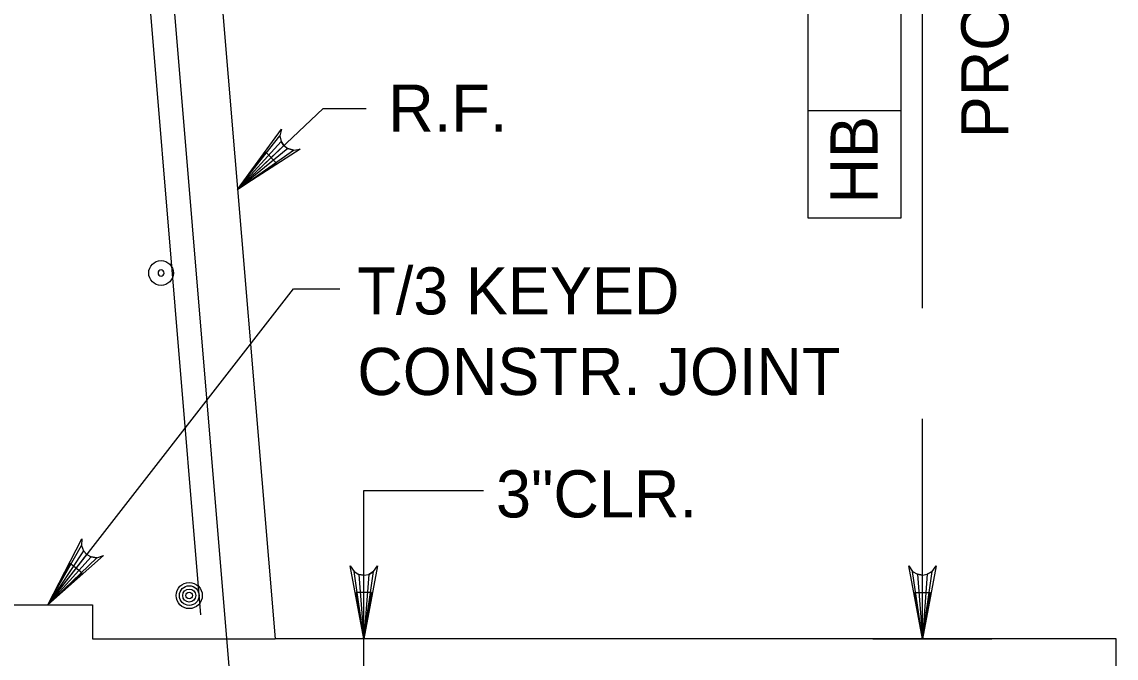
# Model space of a CAD drawing. Extents: x 638255 to 640306, y 296059 to 298435.
# Drawn here: x 639132.2 to 639201.8, y 297021.7 to 297062.2 of the extents above; entities that cross this region are included whole.
import ezdxf

# ---------------------------------------------------------------- set-up
doc = ezdxf.new("R2010")
doc.units = 0
for name, color, linetype in [('3', 7, 'Continuous'), ('Level 3', 7, 'Continuous'), ('Level 4', 7, 'Continuous'), ('Level 5', 7, 'Continuous'), ('Level 6', 7, 'Continuous'), ('Level 7', 7, 'Continuous'), ('Level 9', 7, 'Continuous')]:
    doc.layers.add(name, color=color, linetype=linetype)

# ---------------------------------------------------------------- blocks, each defined once
blk = doc.blocks.new('B')
at = {"layer": '3'}
blk.add_circle((0, 0), 0.16, dxfattribs=at)
for start, end in [(0, 180), (180, 0)]:
    blk.add_arc((0, 0), 0.0391, start, end, dxfattribs=at)

msp = doc.modelspace()

# ---------------------------------------------------------------- linework, layer by layer
at = {"layer": 'Level 3'}
for p, q in [((639189.499, 297043.979), (639189.499, 297093.526)), ((639182.231, 297056.542), (639182.231, 297084.942)), ((639188.123, 297084.942), (639188.123, 297049.709)), ((639145.904, 297051.541), (639151.36, 297056.692)), ((639151.36, 297056.692), (639154.088, 297056.692)), ((639182.231, 297049.709), (639182.231, 297056.542)), ((639188.123, 297056.542), (639182.231, 297056.542)), ((639188.123, 297049.709), (639182.231, 297049.709)), ((639133.823, 297025.106), (639149.464, 297045.222)), ((639149.464, 297045.222), (639152.41, 297045.222)), ((639189.499, 297022.949), (639189.499, 297036.945)), ((639153.939, 297032.379), (639161.559, 297032.379)), ((639186.331, 297022.948), (639193.919, 297022.948))]:
    msp.add_line(p, q, dxfattribs=at)
for points in [[(639145.904, 297051.541), (639148.688, 297055.369), (639148.597, 297054.941), (639148.678, 297054.588), (639148.853, 297054.326), (639149.106, 297054.134), (639149.454, 297054.034), (639149.886, 297054.101), (639145.904, 297051.541), (639149.454, 297054.034), (639149.106, 297054.134), (639145.904, 297051.541), (639148.853, 297054.326), (639148.678, 297054.588), (639145.904, 297051.541), (639148.597, 297054.941)], [(639133.823, 297025.106), (639135.99, 297029.313), (639135.965, 297028.878), (639136.098, 297028.541), (639136.312, 297028.306), (639136.591, 297028.159), (639136.95, 297028.113), (639137.366, 297028.244), (639133.823, 297025.106), (639136.95, 297028.113), (639136.591, 297028.159), (639133.823, 297025.106), (639136.312, 297028.306), (639136.098, 297028.541), (639133.823, 297025.106), (639135.965, 297028.878)], [(639153.939, 297022.94), (639153.067, 297027.591), (639153.315, 297027.234), (639153.627, 297027.048), (639153.939, 297026.994), (639154.251, 297027.048), (639154.563, 297027.234), (639154.81, 297027.591), (639153.939, 297022.94), (639154.563, 297027.234), (639154.251, 297027.048), (639153.939, 297022.94), (639153.939, 297026.994), (639153.627, 297027.048), (639153.939, 297022.94), (639153.315, 297027.234)], [(639189.498, 297022.948), (639188.627, 297027.599), (639188.874, 297027.242), (639189.186, 297027.057), (639189.498, 297027.003), (639189.81, 297027.057), (639190.122, 297027.242), (639190.369, 297027.599), (639189.498, 297022.948), (639190.122, 297027.242), (639189.81, 297027.057), (639189.498, 297022.948), (639189.498, 297027.003), (639189.186, 297027.057), (639189.498, 297022.948), (639188.874, 297027.242)]]:
    msp.add_lwpolyline(points, dxfattribs=at)
for points in [[(639148.385, 297053.205), (639147.709, 297053.92), (639145.904, 297051.539)], [(639136.019, 297027.132), (639135.243, 297027.735), (639133.823, 297025.106)], [(639189.007, 297025.894), (639189.989, 297025.894), (639189.498, 297022.948)]]:
    msp.add_lwpolyline(points, close=True, dxfattribs=at)
at = {"layer": 'Level 4'}
msp.add_line((639153.939, 297019.879), (639153.939, 297032.379), dxfattribs=at)
msp.add_lwpolyline([(639154.429, 297025.888), (639153.448, 297025.888), (639153.939, 297022.94)], close=True, dxfattribs=at)
at = {"layer": 'Level 5'}
for p, q in [((639139.995, 297067.008), (639143.538, 297024.483)), ((639141.506, 297067.349), (639146.655, 297005.577))]:
    msp.add_line(p, q, dxfattribs=at)
for radius in [0.832, 0.624, 0.416, 0.208]:
    msp.add_circle((639142.824, 297025.704), radius, dxfattribs=at)
at = {"layer": 'Level 6'}
msp.add_lwpolyline([(639118.471, 297022.948), (639129.481, 297022.948), (639129.481, 297025.106), (639136.659, 297025.106), (639136.659, 297022.948), (639148.287, 297022.948)], dxfattribs=at)
at = {"layer": 'Level 7'}
for p, q in [((639197.84, 297022.94), (639197.84, 297022.94)), ((639201.592, 297022.94), (639201.592, 297022.94))]:
    msp.add_line(p, q, dxfattribs=at)
at = {"layer": 'Level 9'}
for p, q in [((639136.89, 297159.704), (639148.287, 297022.948)), ((639201.829, 297022.948), (639148.287, 297022.948)), ((639201.829, 296998.389), (639201.829, 297022.948))]:
    msp.add_line(p, q, dxfattribs=at)

# ---------------------------------------------------------------- block references
at = {"layer": 'Level 3', "xscale": 4.911876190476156, "yscale": 4.911876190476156, "rotation": 90}
msp.add_blockref('B', (639141.032, 297046.223), dxfattribs=at)

# ---------------------------------------------------------------- texts
at = {"layer": 'Level 3'}
for s, p in [('PROJECTION', (639194.973, 297054.792)), ('HB', (639186.643, 297050.641))]:
    msp.add_text(s, height=3.0001, rotation=90, dxfattribs=at).set_placement(p)
for s, height, p in [('R.F.', 3.0001, (639155.496, 297055.208)), ('T/3 KEYED', 3.0001, (639153.523, 297043.587)), ('CONSTR. JOINT', 3.00014, (639153.523, 297038.461)), ('3"CLR.', 3.0001, (639162.352, 297030.672))]:
    msp.add_text(s, height=height, dxfattribs=at).set_placement(p)

doc.saveas('drawing.dxf')
